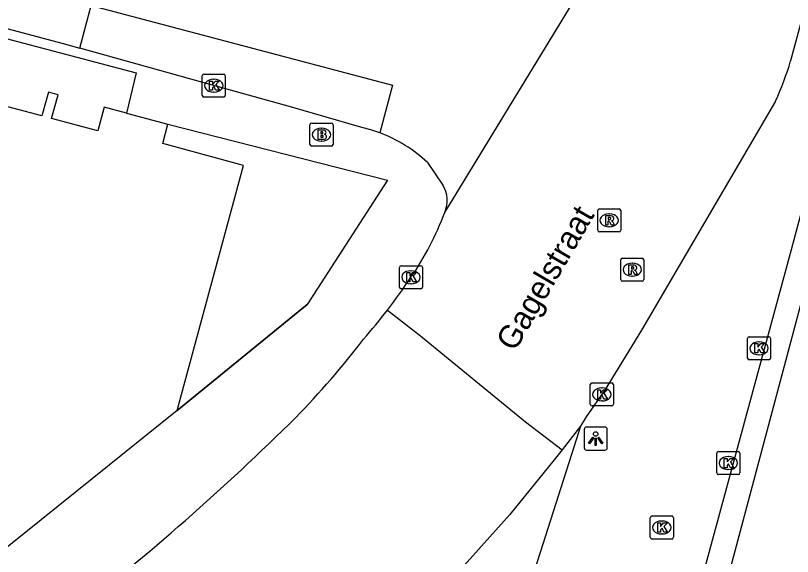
# Model space of a CAD drawing. Extents: x 160676 to 161153, y 383244 to 383713.
# Drawn here: x 160828.58 to 160862.26, y 383517.37 to 383540.83 of the extents above; entities that cross this region are included whole.
import ezdxf

# ---------------------------------------------------------------- set-up
doc = ezdxf.new("R2010")
doc.units = 0
for name, color, linetype in [('IMGEO_Brandkraan', 7, 'Continuous'), ('IMGEO_Kolk', 7, 'Continuous'), ('IMGEO_Lichtpunt', 7, 'Continuous'), ('IMGEO_Muur', 7, 'Continuous'), ('IMGEO_Openbare_ruimte_label', 7, 'Continuous'), ('IMGEO_Pand', 7, 'Continuous'), ('IMGEO_Rijbaan_lokaal_gesloten', 7, 'Continuous'), ('IMGEO_Rijbaan_lokaal_open', 7, 'Continuous'), ('IMGEO_Rioolput', 7, 'Continuous'), ('IMGEO_Voetpad_open', 7, 'Continuous')]:
    doc.layers.add(name, color=color, linetype=linetype)

msp = doc.modelspace()

# ---------------------------------------------------------------- linework, layer by layer
at = {"layer": 'IMGEO_Brandkraan'}
for p, q in [((160841.419, 383536.169), (160842.271, 383536.169)), ((160841.344, 383535.243), (160841.344, 383536.095)), ((160841.832, 383535.949), (160841.857, 383535.949)), ((160842.345, 383536.095), (160842.345, 383535.243)), ((160842.271, 383535.169), (160841.419, 383535.169)), ((160841.855, 383535.389), (160841.83, 383535.389))]:
    msp.add_line(p, q, dxfattribs=at)
for points in [[(160841.419, 383536.169), (160842.271, 383536.169)], [(160841.344, 383535.243), (160841.344, 383536.095)], [(160841.692, 383535.869), (160841.692, 383535.469), (160841.905, 383535.469)], [(160841.923, 383535.869), (160841.692, 383535.869)], [(160841.871, 383535.788), (160841.817, 383535.788), (160841.817, 383535.712)], [(160842.345, 383536.095), (160842.345, 383535.243)], [(160841.817, 383535.712), (160841.87, 383535.712)], [(160841.879, 383535.636), (160841.817, 383535.636), (160841.817, 383535.555)], [(160841.817, 383535.555), (160841.879, 383535.555)], [(160842.271, 383535.169), (160841.419, 383535.169)]]:
    msp.add_lwpolyline(points, dxfattribs=at)
for centre, radius, start, end in [((160841.421, 383536.093), 0.0765, 91.552, 178.448), ((160841.421, 383536.093), 0.0765, 91.552, 178.448), ((160842.269, 383536.093), 0.0765, 1.552, 88.448), ((160842.269, 383536.093), 0.0765, 1.552, 88.448), ((160841.872, 383535.75), 0.0379, 267.8285, 90.9355), ((160841.927, 383535.724), 0.145, 59.4692, 91.5367), ((160841.952, 383535.771), 0.0922, 285.5137, 58.1501), ((160841.88, 383535.595), 0.0404, 269.8759, 90.5077), ((160841.911, 383535.72), 0.251, 268.6676, 293.5347), ((160841.957, 383535.579), 0.105, 301.3115, 78.989), ((160841.421, 383535.245), 0.0765, 181.552, 268.448), ((160841.421, 383535.245), 0.0765, 181.552, 268.448), ((160842.269, 383535.245), 0.0765, 271.552, 358.448), ((160842.269, 383535.245), 0.0765, 271.552, 358.448)]:
    msp.add_arc(centre, radius, start, end, dxfattribs=at)
for centre, major_axis, ratio, start_param, end_param in [((160841.831, 383535.669), (-0.387, 0.002), 0.722429, 4.712389, 7.853982), ((160841.856, 383535.669), (-0.39, 0.002), 0.717154, 1.570796, 4.712389)]:
    msp.add_ellipse(centre, major_axis=major_axis, ratio=ratio, start_param=start_param, end_param=end_param, dxfattribs=at)
at = {"layer": 'IMGEO_Kolk'}
for p, q in [((160836.673, 383537.369), (160836.673, 383538.221)), ((160836.748, 383538.295), (160837.6, 383538.295)), ((160837.674, 383538.221), (160837.674, 383537.369)), ((160837.161, 383538.075), (160837.186, 383538.075)), ((160837.184, 383537.515), (160837.159, 383537.515)), ((160837.6, 383537.295), (160836.748, 383537.295)), ((160845.224, 383529.057), (160845.224, 383529.909)), ((160845.299, 383529.983), (160846.151, 383529.983)), ((160845.712, 383529.763), (160845.737, 383529.763)), ((160846.225, 383529.909), (160846.225, 383529.057)), ((160845.735, 383529.203), (160845.71, 383529.203)), ((160846.151, 383528.983), (160845.299, 383528.983)), ((160860.314, 383525.976), (160860.314, 383526.828)), ((160860.389, 383526.902), (160861.241, 383526.902)), ((160860.802, 383526.682), (160860.827, 383526.682)), ((160861.315, 383526.828), (160861.315, 383525.976)), ((160860.825, 383526.122), (160860.8, 383526.122)), ((160861.241, 383525.902), (160860.389, 383525.902)), ((160853.499, 383523.974), (160853.499, 383524.826)), ((160853.574, 383524.9), (160854.426, 383524.9)), ((160853.987, 383524.68), (160854.012, 383524.68)), ((160854.5, 383524.826), (160854.5, 383523.974)), ((160854.01, 383524.12), (160853.985, 383524.12)), ((160854.426, 383523.9), (160853.574, 383523.9)), ((160858.982, 383520.997), (160858.982, 383521.849)), ((160859.057, 383521.923), (160859.909, 383521.923)), ((160859.47, 383521.703), (160859.495, 383521.703)), ((160859.983, 383521.849), (160859.983, 383520.997)), ((160859.493, 383521.143), (160859.468, 383521.143)), ((160859.909, 383520.923), (160859.057, 383520.923)), ((160856.101, 383518.202), (160856.101, 383519.054)), ((160856.176, 383519.128), (160857.028, 383519.128)), ((160857.102, 383519.054), (160857.102, 383518.202)), ((160856.589, 383518.908), (160856.614, 383518.908)), ((160856.612, 383518.348), (160856.587, 383518.348)), ((160857.028, 383518.128), (160856.176, 383518.128))]:
    msp.add_line(p, q, dxfattribs=at)
for points in [[(160836.673, 383537.369), (160836.673, 383538.221)], [(160836.748, 383538.295), (160837.6, 383538.295)], [(160837.674, 383538.221), (160837.674, 383537.369)], [(160836.994, 383537.995), (160837.117, 383537.995), (160837.117, 383537.844), (160837.247, 383537.995), (160837.411, 383537.995), (160837.265, 383537.844), (160837.418, 383537.595), (160837.266, 383537.595), (160837.181, 383537.759), (160837.117, 383537.692), (160837.117, 383537.595), (160836.994, 383537.595), (160836.994, 383537.995)], [(160837.6, 383537.295), (160836.748, 383537.295)], [(160845.224, 383529.057), (160845.224, 383529.909)], [(160845.299, 383529.983), (160846.151, 383529.983)], [(160846.225, 383529.909), (160846.225, 383529.057)], [(160845.545, 383529.683), (160845.668, 383529.683), (160845.668, 383529.532), (160845.798, 383529.683), (160845.962, 383529.683), (160845.816, 383529.532), (160845.969, 383529.283), (160845.817, 383529.283), (160845.732, 383529.447), (160845.668, 383529.38), (160845.668, 383529.283), (160845.545, 383529.283), (160845.545, 383529.683)], [(160846.151, 383528.983), (160845.299, 383528.983)], [(160860.314, 383525.976), (160860.314, 383526.828)], [(160860.389, 383526.902), (160861.241, 383526.902)], [(160861.315, 383526.828), (160861.315, 383525.976)], [(160860.635, 383526.602), (160860.758, 383526.602), (160860.758, 383526.451), (160860.888, 383526.602), (160861.052, 383526.602), (160860.906, 383526.451), (160861.059, 383526.202), (160860.907, 383526.202), (160860.822, 383526.366), (160860.758, 383526.299), (160860.758, 383526.202), (160860.635, 383526.202), (160860.635, 383526.602)], [(160861.241, 383525.902), (160860.389, 383525.902)], [(160853.499, 383523.974), (160853.499, 383524.826)], [(160853.574, 383524.9), (160854.426, 383524.9)], [(160854.5, 383524.826), (160854.5, 383523.974)], [(160853.82, 383524.6), (160853.943, 383524.6), (160853.943, 383524.449), (160854.073, 383524.6), (160854.237, 383524.6), (160854.091, 383524.449), (160854.244, 383524.2), (160854.092, 383524.2), (160854.007, 383524.364), (160853.943, 383524.297), (160853.943, 383524.2), (160853.82, 383524.2), (160853.82, 383524.6)], [(160854.426, 383523.9), (160853.574, 383523.9)], [(160858.982, 383520.997), (160858.982, 383521.849)], [(160859.057, 383521.923), (160859.909, 383521.923)], [(160859.983, 383521.849), (160859.983, 383520.997)], [(160859.303, 383521.623), (160859.426, 383521.623), (160859.426, 383521.472), (160859.556, 383521.623), (160859.72, 383521.623), (160859.574, 383521.472), (160859.727, 383521.223), (160859.575, 383521.223), (160859.49, 383521.387), (160859.426, 383521.32), (160859.426, 383521.223), (160859.303, 383521.223), (160859.303, 383521.623)], [(160859.909, 383520.923), (160859.057, 383520.923)], [(160856.101, 383518.202), (160856.101, 383519.054)], [(160856.176, 383519.128), (160857.028, 383519.128)], [(160857.102, 383519.054), (160857.102, 383518.202)], [(160856.422, 383518.828), (160856.545, 383518.828), (160856.545, 383518.677), (160856.675, 383518.828), (160856.839, 383518.828), (160856.693, 383518.677), (160856.846, 383518.428), (160856.694, 383518.428), (160856.609, 383518.592), (160856.545, 383518.525), (160856.545, 383518.428), (160856.422, 383518.428), (160856.422, 383518.828)], [(160857.028, 383518.128), (160856.176, 383518.128)]]:
    msp.add_lwpolyline(points, dxfattribs=at)
for centre, start, end in [((160836.75, 383538.219), 91.552, 178.448), ((160836.75, 383538.219), 91.552, 178.448), ((160837.598, 383538.219), 1.552, 88.448), ((160837.598, 383538.219), 1.552, 88.448), ((160836.75, 383537.371), 181.552, 268.448), ((160836.75, 383537.371), 181.552, 268.448), ((160837.598, 383537.371), 271.552, 358.448), ((160837.598, 383537.371), 271.552, 358.448), ((160845.301, 383529.907), 91.552, 178.448), ((160845.301, 383529.907), 91.552, 178.448), ((160846.149, 383529.907), 1.552, 88.448), ((160846.149, 383529.907), 1.552, 88.448), ((160845.301, 383529.059), 181.552, 268.448), ((160845.301, 383529.059), 181.552, 268.448), ((160846.149, 383529.059), 271.552, 358.448), ((160846.149, 383529.059), 271.552, 358.448), ((160860.391, 383526.826), 91.552, 178.448), ((160860.391, 383526.826), 91.552, 178.448), ((160861.239, 383526.826), 1.552, 88.448), ((160861.239, 383526.826), 1.552, 88.448), ((160860.391, 383525.978), 181.552, 268.448), ((160860.391, 383525.978), 181.552, 268.448), ((160861.239, 383525.978), 271.552, 358.448), ((160861.239, 383525.978), 271.552, 358.448), ((160853.576, 383524.824), 91.552, 178.448), ((160853.576, 383524.824), 91.552, 178.448), ((160854.424, 383524.824), 1.552, 88.448), ((160854.424, 383524.824), 1.552, 88.448), ((160853.576, 383523.976), 181.552, 268.448), ((160853.576, 383523.976), 181.552, 268.448), ((160854.424, 383523.976), 271.552, 358.448), ((160854.424, 383523.976), 271.552, 358.448), ((160859.059, 383521.847), 91.552, 178.448), ((160859.059, 383521.847), 91.552, 178.448), ((160859.907, 383521.847), 1.552, 88.448), ((160859.907, 383521.847), 1.552, 88.448), ((160859.059, 383520.999), 181.552, 268.448), ((160859.059, 383520.999), 181.552, 268.448), ((160859.907, 383520.999), 271.552, 358.448), ((160859.907, 383520.999), 271.552, 358.448), ((160856.178, 383519.052), 91.552, 178.448), ((160856.178, 383519.052), 91.552, 178.448), ((160857.026, 383519.052), 1.552, 88.448), ((160857.026, 383519.052), 1.552, 88.448), ((160856.178, 383518.204), 181.552, 268.448), ((160856.178, 383518.204), 181.552, 268.448), ((160857.026, 383518.204), 271.552, 358.448), ((160857.026, 383518.204), 271.552, 358.448)]:
    msp.add_arc(centre, 0.0765, start, end, dxfattribs=at)
for centre, major_axis, ratio, start_param, end_param in [((160837.16, 383537.795), (-0.387, 0.002), 0.722429, 4.712389, 7.853982), ((160837.185, 383537.795), (-0.39, 0.002), 0.717154, 1.570796, 4.712389), ((160845.711, 383529.483), (-0.387, 0.002), 0.722429, 4.712389, 7.853982), ((160845.736, 383529.483), (-0.39, 0.002), 0.717154, 1.570796, 4.712389), ((160860.801, 383526.402), (-0.387, 0.002), 0.722429, 4.712389, 7.853982), ((160860.826, 383526.402), (-0.39, 0.002), 0.717154, 1.570796, 4.712389), ((160853.986, 383524.4), (-0.387, 0.002), 0.722429, 4.712389, 7.853982), ((160854.011, 383524.4), (-0.39, 0.002), 0.717154, 1.570796, 4.712389), ((160859.469, 383521.423), (-0.387, 0.002), 0.722429, 4.712389, 7.853982), ((160859.494, 383521.423), (-0.39, 0.002), 0.717154, 1.570796, 4.712389), ((160856.588, 383518.628), (-0.387, 0.002), 0.722429, 4.712389, 7.853982), ((160856.613, 383518.628), (-0.39, 0.002), 0.717154, 1.570796, 4.712389)]:
    msp.add_ellipse(centre, major_axis=major_axis, ratio=ratio, start_param=start_param, end_param=end_param, dxfattribs=at)
at = {"layer": 'IMGEO_Lichtpunt'}
for p, q in [((160854.136, 383522.982), (160853.328, 383522.982)), ((160854.136, 383522.982), (160853.328, 383522.982)), ((160853.234, 383522.887), (160853.234, 383522.08)), ((160853.234, 383522.887), (160853.234, 383522.08)), ((160854.23, 383522.08), (160854.23, 383522.887)), ((160854.23, 383522.08), (160854.23, 383522.887)), ((160853.328, 383521.986), (160854.136, 383521.986)), ((160853.328, 383521.986), (160854.136, 383521.986))]:
    msp.add_line(p, q, dxfattribs=at)
for points in [[(160853.608, 383522.551), (160853.647, 383522.523), (160853.459, 383522.261), (160853.421, 383522.288), (160853.608, 383522.551)], [(160853.71, 383522.503), (160853.757, 383522.503), (160853.757, 383522.181), (160853.71, 383522.181), (160853.71, 383522.503)], [(160853.82, 383522.523), (160853.858, 383522.55), (160854.045, 383522.288), (160854.006, 383522.26), (160853.82, 383522.523)]]:
    msp.add_lwpolyline(points, dxfattribs=at)
msp.add_circle((160853.733, 383522.685), 0.0994, dxfattribs=at)
for centre, start, end in [((160853.328, 383522.887), 90, 180), ((160853.328, 383522.887), 90, 180), ((160854.136, 383522.887), 0, 90), ((160854.136, 383522.887), 0, 90), ((160853.328, 383522.08), 180, 270), ((160853.328, 383522.08), 180, 270), ((160854.136, 383522.08), 270, 0), ((160854.136, 383522.08), 270, 360)]:
    msp.add_arc(centre, 0.0946, start, end, dxfattribs=at)
at = {"layer": 'IMGEO_Muur'}
msp.add_lwpolyline([(160835.583, 383523.701), (160841.228, 383528.297)], dxfattribs=at)
at = {"layer": 'IMGEO_Pand'}
for points in [[(160858.445, 383512.624), (160866.56, 383543.07), (160867.863, 383547.958), (160869.136, 383548.269), (160882.404, 383551.516)], [(160833.395, 383536.594), (160832.418, 383536.856), (160832.143, 383535.833), (160830.138, 383536.367), (160830.422, 383537.388), (160830.007, 383537.504), (160829.722, 383536.483), (160827.746, 383537.005), (160828.012, 383538.031), (160827.604, 383538.137), (160827.337, 383537.111), (160825.342, 383537.638), (160825.617, 383538.662), (160824.365, 383538.998)], [(160833.395, 383536.594), (160835.176, 383536.116)], [(160835.583, 383523.701), (160838.46, 383534.331), (160834.961, 383535.279), (160835.176, 383536.116)], [(160835.583, 383523.701), (160818.62, 383510.07), (160814.473, 383508.308), (160792.502, 383498.971)]]:
    msp.add_lwpolyline(points, dxfattribs=at)
at = {"layer": 'IMGEO_Rijbaan_lokaal_gesloten'}
for points in [[(160853.08, 383523.019), (160852.899, 383522.475), (160851.327, 383517.544), (160850.446, 383514.813), (160850.389, 383514.634)], [(160853.08, 383523.019), (160852.278, 383522.002)], [(160852.278, 383522.002), (160851.928, 383521.559), (160850.016, 383519.196), (160847.537, 383516.432), (160846.192, 383515.136), (160844.956, 383511.246), (160830.761, 383466.58), (160830.058, 383464.081)]]:
    msp.add_lwpolyline(points, dxfattribs=at)
at = {"layer": 'IMGEO_Rijbaan_lokaal_open'}
for points in [[(160868.559, 383562.537), (160865.424, 383550.899), (160862.182, 383538.869)], [(160847.186, 383532.297), (160854.151, 383543.734), (160854.265, 383544.033)], [(160831.364, 383539.424), (160831.855, 383541.275), (160844.921, 383537.811), (160844.373, 383535.746)], [(160827.531, 383540.452), (160830.643, 383539.626), (160831.364, 383539.424)], [(160861.525, 383537.121), (160855.717, 383527.187), (160854.143, 383524.612), (160853.325, 383523.422), (160853.08, 383523.019)], [(160846.439, 383534.458), (160847.108, 383533.477)], [(160844.705, 383528.06), (160846.137, 383526.942), (160850.693, 383523.206), (160852.278, 383522.002)]]:
    msp.add_lwpolyline(points, dxfattribs=at)
for centre, radius, start, end in [((160850.804, 383542.148), 11.842, 334.8784, 343.9233), ((160842.201, 383529.961), 6.179, 46.6981, 69.4209), ((160846.045, 383532.814), 1.253, 335.6154, 31.9483), ((160834.957, 383536.856), 13.052, 325.5874, 339.5547), ((160821.173, 383546.022), 29.604, 322.645, 326.0282)]:
    msp.add_arc(centre, radius, start, end, dxfattribs=at)
at = {"layer": 'IMGEO_Rioolput'}
for p, q in [((160853.894, 383532.45), (160854.746, 383532.45)), ((160853.819, 383531.524), (160853.819, 383532.376)), ((160854.307, 383532.23), (160854.332, 383532.23)), ((160854.82, 383532.376), (160854.82, 383531.524)), ((160854.746, 383531.45), (160853.894, 383531.45)), ((160854.33, 383531.67), (160854.305, 383531.67)), ((160854.819, 383529.384), (160854.819, 383530.236)), ((160854.894, 383530.31), (160855.746, 383530.31)), ((160855.307, 383530.09), (160855.332, 383530.09)), ((160855.82, 383530.236), (160855.82, 383529.384)), ((160855.33, 383529.53), (160855.305, 383529.53)), ((160855.746, 383529.31), (160854.894, 383529.31))]:
    msp.add_line(p, q, dxfattribs=at)
for points in [[(160853.894, 383532.45), (160854.746, 383532.45)], [(160853.819, 383531.524), (160853.819, 383532.376)], [(160854.408, 383532.148), (160854.156, 383532.15), (160854.156, 383531.75)], [(160854.334, 383532.069), (160854.28, 383532.069), (160854.28, 383531.988)], [(160854.82, 383532.376), (160854.82, 383531.524)], [(160854.156, 383531.75), (160854.28, 383531.75), (160854.28, 383531.912), (160854.291, 383531.912)], [(160854.28, 383531.988), (160854.332, 383531.988)], [(160854.338, 383531.883), (160854.409, 383531.75), (160854.549, 383531.75), (160854.484, 383531.876)], [(160854.746, 383531.45), (160853.894, 383531.45)], [(160854.819, 383529.384), (160854.819, 383530.236)], [(160854.894, 383530.31), (160855.746, 383530.31)], [(160855.82, 383530.236), (160855.82, 383529.384)], [(160855.408, 383530.008), (160855.156, 383530.01), (160855.156, 383529.61)], [(160855.156, 383529.61), (160855.28, 383529.61), (160855.28, 383529.772), (160855.291, 383529.772)], [(160855.334, 383529.929), (160855.28, 383529.929), (160855.28, 383529.848)], [(160855.28, 383529.848), (160855.332, 383529.848)], [(160855.338, 383529.743), (160855.409, 383529.61), (160855.549, 383529.61), (160855.484, 383529.736)], [(160855.746, 383529.31), (160854.894, 383529.31)]]:
    msp.add_lwpolyline(points, dxfattribs=at)
for centre, radius, start, end in [((160853.896, 383532.374), 0.0765, 91.552, 178.448), ((160853.896, 383532.374), 0.0765, 91.552, 178.448), ((160854.744, 383532.374), 0.0765, 1.552, 88.448), ((160854.744, 383532.374), 0.0765, 1.552, 88.448), ((160854.34, 383531.973), 0.0964, 77.0061, 93.1865), ((160854.407, 383532.038), 0.109, 350.3612, 89.416), ((160854.29, 383531.859), 0.0533, 26.0293, 88.6989), ((160854.316, 383532.177), 0.19, 274.7715, 282.9687), ((160854.354, 383532.03), 0.0378, 276.6634, 79.6772), ((160854.405, 383532.038), 0.112, 277.5842, 350.9817), ((160854.389, 383531.823), 0.108, 29.5134, 73.7905), ((160853.896, 383531.526), 0.0765, 181.552, 268.448), ((160853.896, 383531.526), 0.0765, 181.552, 268.448), ((160854.744, 383531.526), 0.0765, 271.552, 358.448), ((160854.744, 383531.526), 0.0765, 271.552, 358.448), ((160854.896, 383530.234), 0.0765, 91.552, 178.448), ((160854.896, 383530.234), 0.0765, 91.552, 178.448), ((160855.744, 383530.234), 0.0765, 1.552, 88.448), ((160855.744, 383530.234), 0.0765, 1.552, 88.448), ((160855.29, 383529.719), 0.0533, 26.0293, 88.6989), ((160855.316, 383530.037), 0.19, 274.7715, 282.9687), ((160855.34, 383529.833), 0.0964, 77.0061, 93.1865), ((160855.354, 383529.89), 0.0378, 276.6634, 79.6772), ((160855.407, 383529.898), 0.109, 350.3612, 89.416), ((160855.405, 383529.898), 0.112, 277.5842, 350.9817), ((160855.389, 383529.683), 0.108, 29.5134, 73.7905), ((160854.896, 383529.386), 0.0765, 181.552, 268.448), ((160854.896, 383529.386), 0.0765, 181.552, 268.448), ((160855.744, 383529.386), 0.0765, 271.552, 358.448), ((160855.744, 383529.386), 0.0765, 271.552, 358.448)]:
    msp.add_arc(centre, radius, start, end, dxfattribs=at)
for centre, major_axis, ratio, start_param, end_param in [((160854.306, 383531.95), (-0.387, 0.002), 0.722429, 4.712389, 7.853982), ((160854.331, 383531.95), (-0.39, 0.002), 0.717154, 1.570796, 4.712389), ((160855.306, 383529.81), (-0.387, 0.002), 0.722429, 4.712389, 7.853982), ((160855.331, 383529.81), (-0.39, 0.002), 0.717154, 1.570796, 4.712389)]:
    msp.add_ellipse(centre, major_axis=major_axis, ratio=ratio, start_param=start_param, end_param=end_param, dxfattribs=at)
at = {"layer": 'IMGEO_Voetpad_open'}
for points in [[(160857.402, 383512.924), (160862.229, 383530.692), (160867.046, 383548.766)], [(160824.365, 383538.998), (160824.823, 383540.726), (160833.805, 383538.352), (160833.395, 383536.594)], [(160844.373, 383535.746), (160843.986, 383535.876), (160843.592, 383535.981), (160840.505, 383536.875), (160836.079, 383538.099), (160831.364, 383539.424)], [(160835.176, 383536.116), (160844.706, 383533.691), (160841.228, 383528.297), (160835.583, 383523.701)]]:
    msp.add_lwpolyline(points, dxfattribs=at)
for centre, radius, start, end in [((160824.375, 383543.748), 25.68, 318.6799, 322.3435), ((160815.28, 383548.354), 35.642, 315.5668, 322.7757), ((160761.862, 383603.196), 112.194, 307.97923, 314.6661)]:
    msp.add_arc(centre, radius, start, end, dxfattribs=at)

# ---------------------------------------------------------------- texts
at = {"layer": 'IMGEO_Openbare_ruimte_label'}
msp.add_text('Gagelstraat', height=1, rotation=59.7931, dxfattribs=at).set_placement((160850.224, 383526.218))

doc.saveas('drawing.dxf')
